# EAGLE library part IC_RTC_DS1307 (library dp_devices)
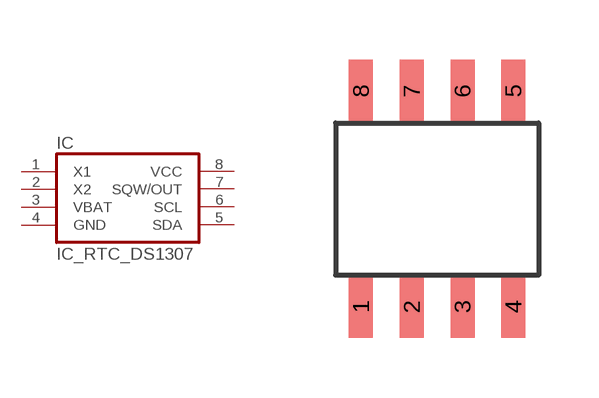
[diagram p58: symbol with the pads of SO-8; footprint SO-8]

Designator prefix IC

## IC_RTC_DS1307  [SO-8]
1  X1
2  X2
3  VBAT
4  GND
5  SDA
6  SCL
7  SQW/OUT
8  VCC

## Footprint SO-8 (pad centres in mm)
smd 0.6 x 1.55: 1 -1.905,-2.69; 2 -0.635,-2.69; 3 0.635,-2.69; 4 1.905,-2.69; 5 1.905,2.71; 6 0.635,2.71; 7 -0.635,2.71; 8 -1.905,2.71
